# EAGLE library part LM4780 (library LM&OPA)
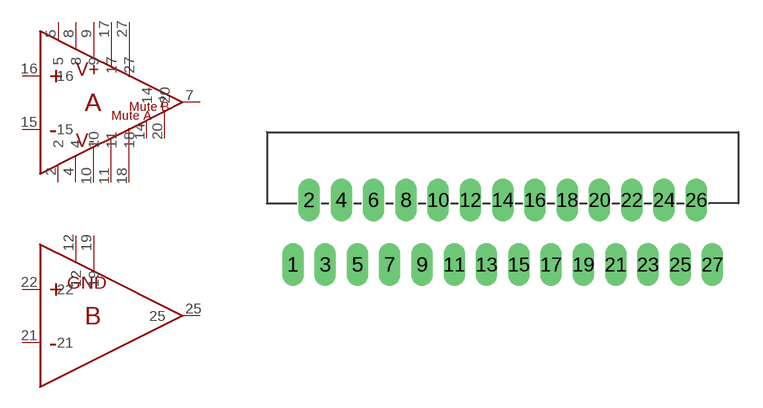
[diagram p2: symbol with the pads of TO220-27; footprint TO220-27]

Designator prefix -

## LM4780  [TO220-27]
2  2  pwr
4  4  pwr
5  5  pwr
7  7  out
8  8  pwr
9  9  pwr
10  10  pwr
11  11  pwr
12  12  pwr
14  14
15  15  in
16  16  in
17  17  pwr
18  18  pwr
19  19  pwr
20  20
21  21  in
22  22  in
25  25  out
27  27  pwr

## Footprint TO220-27 (pad centres in mm)
drill 0.813 pad 1.27 long: 1 -13,-2; 2 -12,2; 3 -11,-2; 4 -10,2; 5 -9,-2; 6 -8,2; 7 -7,-2; 8 -6,2; 9 -5,-2; 10 -4,2; 11 -3,-2; 12 -2,2; 13 -1,-2; 14 0,2; 15 1,-2; 16 2,2; 17 3,-2; 18 4,2; 19 5,-2; 20 6,2; 21 7,-2; 22 8,2; 23 9,-2; 24 10,2; 25 11,-2; 26 12,2; 27 13,-2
